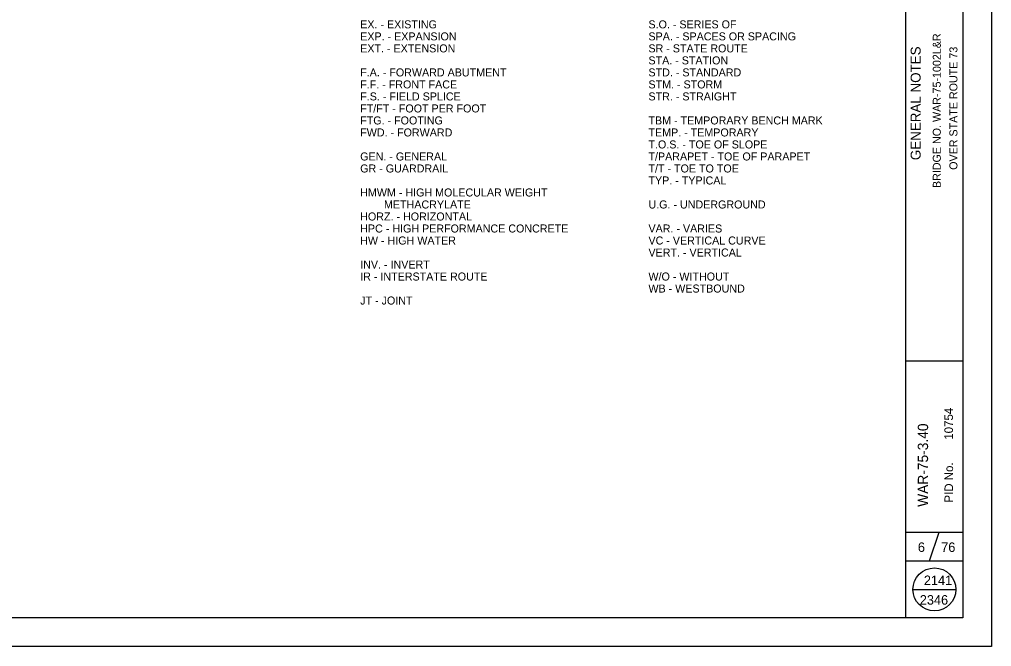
# Model space of a CAD drawing. Extents: x 0 to 34, y 0 to 22.
# Drawn here: x 17 to 34, y 0 to 10.97 of the extents above; entities that cross this region are included whole.
import ezdxf

# ---------------------------------------------------------------- set-up
doc = ezdxf.new("R2010")
doc.units = 0
for name, color, linetype in [('BR_P_Sub_Text', 7, 'Continuous'), ('SH_Border', 7, 'Continuous'), ('SH_Cut_Line', 7, 'Continuous'), ('SH_Data', 7, 'Continuous')]:
    doc.layers.add(name, color=color, linetype=linetype)

msp = doc.modelspace()

# ---------------------------------------------------------------- linework, layer by layer
at = {"layer": 'SH_Border'}
for p, q in [((32.5, 0.5), (32.5, 21.5)), ((32.5, 0.5), (32.5, 21.5)), ((32.5, 0.5), (32.5, 21.5)), ((32.5, 5), (33.5, 5)), ((32.5, 5), (33.5, 5)), ((32.5, 5), (33.5, 5)), ((32.5, 2), (33.5, 2)), ((32.917, 1.5), (33.083, 2)), ((32.5, 1.5), (33.5, 1.5))]:
    msp.add_line(p, q, dxfattribs=at)
msp.add_lwpolyline([(2, 21.5), (33.5, 21.5), (33.5, 0.5), (2, 0.5)], close=True, dxfattribs=at)
at = {"layer": 'SH_Cut_Line'}
msp.add_lwpolyline([(0, 22), (34, 22), (34, 0), (0, 0)], close=True, dxfattribs=at)
at = {"layer": 'SH_Data'}
msp.add_line((32.625, 1), (33.375, 1), dxfattribs=at)
msp.add_line((32.625, 1), (33.375, 1), dxfattribs=at)
msp.add_line((32.625, 1), (33.375, 1), dxfattribs=at)
msp.add_circle((33, 1), 0.375, dxfattribs=at)

# ---------------------------------------------------------------- texts
at = {"layer": 'BR_P_Sub_Text'}
msp.add_text('WAR-75-3.40', height=0.18, rotation=90, dxfattribs=at).set_placement((32.89, 2.444))
at = {"layer": 'SH_Data'}
for s, height, p in [('EX. - EXISTING', 0.14, (22.959, 10.812)), ('S.O. - SERIES OF', 0.14, (28, 10.812)), ('EXP. - EXPANSION', 0.14, (22.959, 10.602)), ('SPA. - SPACES OR SPACING', 0.14, (28, 10.602)), ('EXT. - EXTENSION', 0.14, (22.959, 10.392)), ('SR - STATE ROUTE', 0.14, (28, 10.392)), ('STA. - STATION', 0.14, (28, 10.182)), ('F.A. - FORWARD ABUTMENT', 0.14, (22.959, 9.972)), ('STD. - STANDARD', 0.14, (28, 9.972)), ('F.F. - FRONT FACE', 0.14, (22.959, 9.762)), ('STM. - STORM', 0.14, (28, 9.762)), ('F.S. - FIELD SPLICE', 0.14, (22.959, 9.552)), ('STR. - STRAIGHT', 0.14, (28, 9.552)), ('FT/FT - FOOT PER FOOT', 0.14, (22.959, 9.342)), ('FTG. - FOOTING', 0.14, (22.959, 9.132)), ('TBM - TEMPORARY BENCH MARK', 0.14, (28, 9.132)), ('FWD. - FORWARD', 0.14, (22.959, 8.922)), ('TEMP. - TEMPORARY', 0.14, (28, 8.922)), ('T.O.S. - TOE OF SLOPE', 0.14, (28, 8.712)), ('GEN. - GENERAL', 0.14, (22.959, 8.502)), ('T/PARAPET - TOE OF PARAPET', 0.14, (28, 8.502)), ('GR - GUARDRAIL', 0.14, (22.959, 8.292)), ('T/T - TOE TO TOE', 0.14, (28, 8.292)), ('TYP. - TYPICAL', 0.14, (28, 8.082)), ('HMWM - HIGH MOLECULAR WEIGHT', 0.14, (22.959, 7.872)), ('        METHACRYLATE', 0.14, (22.959, 7.662)), ('U.G. - UNDERGROUND', 0.14, (28, 7.662)), ('HORZ. - HORIZONTAL', 0.14, (22.959, 7.452)), ('HPC - HIGH PERFORMANCE CONCRETE', 0.14, (22.959, 7.242)), ('VAR. - VARIES', 0.14, (28, 7.242)), ('HW - HIGH WATER', 0.14, (22.959, 7.032)), ('VC - VERTICAL CURVE', 0.14, (28, 7.032)), ('VERT. - VERTICAL', 0.14, (28, 6.822)), ('INV. - INVERT', 0.14, (22.959, 6.612)), ('IR - INTERSTATE ROUTE', 0.14, (22.959, 6.402)), ('W/O - WITHOUT', 0.14, (28, 6.402)), ('WB - WESTBOUND', 0.14, (28, 6.192)), ('JT - JOINT', 0.14, (22.959, 5.982)), ('6', 0.167, (32.711, 1.655)), ('76', 0.1666, (33.119, 1.655)), ('2141', 0.1666, (32.816, 1.075)), ('2346', 0.1666, (32.745, 0.733))]:
    msp.add_text(s, height=height, dxfattribs=at).set_placement(p)
for s, height, p in [('BRIDGE NO. WAR-75-1002L&R', 0.14, (33.112, 8.02)), ('GENERAL NOTES', 0.175, (32.76, 8.507)), ('OVER STATE ROUTE 73', 0.14, (33.403, 8.338)), ('10754', 0.15, (33.325, 3.618)), ('PID No.', 0.15, (33.327, 2.519))]:
    msp.add_text(s, height=height, rotation=90, dxfattribs=at).set_placement(p)

doc.saveas('drawing.dxf')
